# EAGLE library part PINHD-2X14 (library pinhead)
PIN HEADER
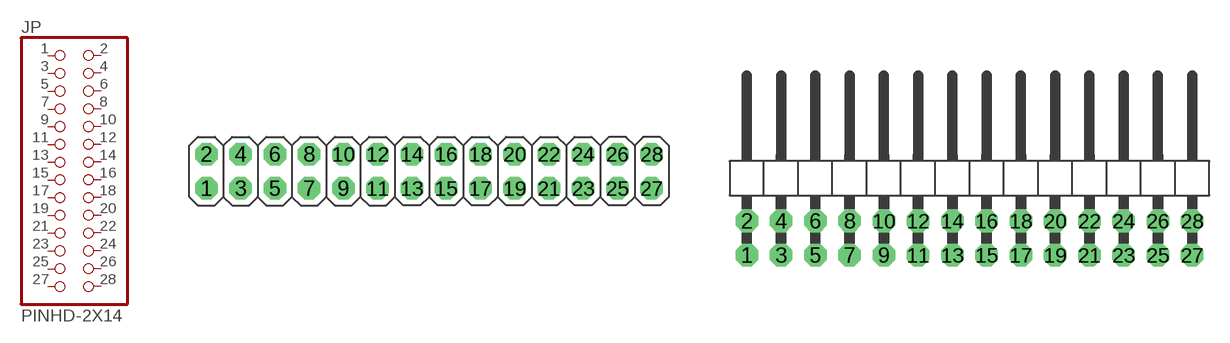
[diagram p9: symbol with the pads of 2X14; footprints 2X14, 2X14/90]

Designator prefix JP

## PINHD-2X14  [2X14]
1  1  pas
2  2  pas
3  3  pas
4  4  pas
5  5  pas
6  6  pas
7  7  pas
8  8  pas
9  9  pas
10  10  pas
11  11  pas
12  12  pas
13  13  pas
14  14  pas
15  15  pas
16  16  pas
17  17  pas
18  18  pas
19  19  pas
20  20  pas
21  21  pas
22  22  pas
23  23  pas
24  24  pas
25  25  pas
26  26  pas
27  27  pas
28  28  pas

## PINHD-2X14/90  [2X14/90]
Pads as for 2X14

## Footprint 2X14 (pad centres in mm)
PIN HEADER
drill 1.016 pad 1.67 octagon: 1 -16.51,-1.27; 2 -16.51,1.27; 3 -13.97,-1.27; 4 -13.97,1.27; 5 -11.43,-1.27; 6 -11.43,1.27; 7 -8.89,-1.27; 8 -8.89,1.27; 9 -6.35,-1.27; 10 -6.35,1.27; 11 -3.81,-1.27; 12 -3.81,1.27; 13 -1.27,-1.27; 14 -1.27,1.27; 15 1.27,-1.27; 16 1.27,1.27; 17 3.81,-1.27; 18 3.81,1.27; 19 6.35,-1.27; 20 6.35,1.27; 21 8.89,-1.27; 22 8.89,1.27; 23 11.43,-1.27; 24 11.43,1.27; 25 13.97,-1.27; 26 13.97,1.27; 27 16.51,-1.27; 28 16.51,1.27

## Footprint 2X14/90 (pad centres in mm)
PIN HEADER
drill 1.016 pad 1.67 octagon: 1 -16.51,-6.35; 2 -16.51,-3.81; 3 -13.97,-6.35; 4 -13.97,-3.81; 5 -11.43,-6.35; 6 -11.43,-3.81; 7 -8.89,-6.35; 8 -8.89,-3.81; 9 -6.35,-6.35; 10 -6.35,-3.81; 11 -3.81,-6.35; 12 -3.81,-3.81; 13 -1.27,-6.35; 14 -1.27,-3.81; 15 1.27,-6.35; 16 1.27,-3.81; 17 3.81,-6.35; 18 3.81,-3.81; 19 6.35,-6.35; 20 6.35,-3.81; 21 8.89,-6.35; 22 8.89,-3.81; 23 11.43,-6.35; 24 11.43,-3.81; 25 13.97,-6.35; 26 13.97,-3.81; 27 16.51,-6.35; 28 16.51,-3.81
